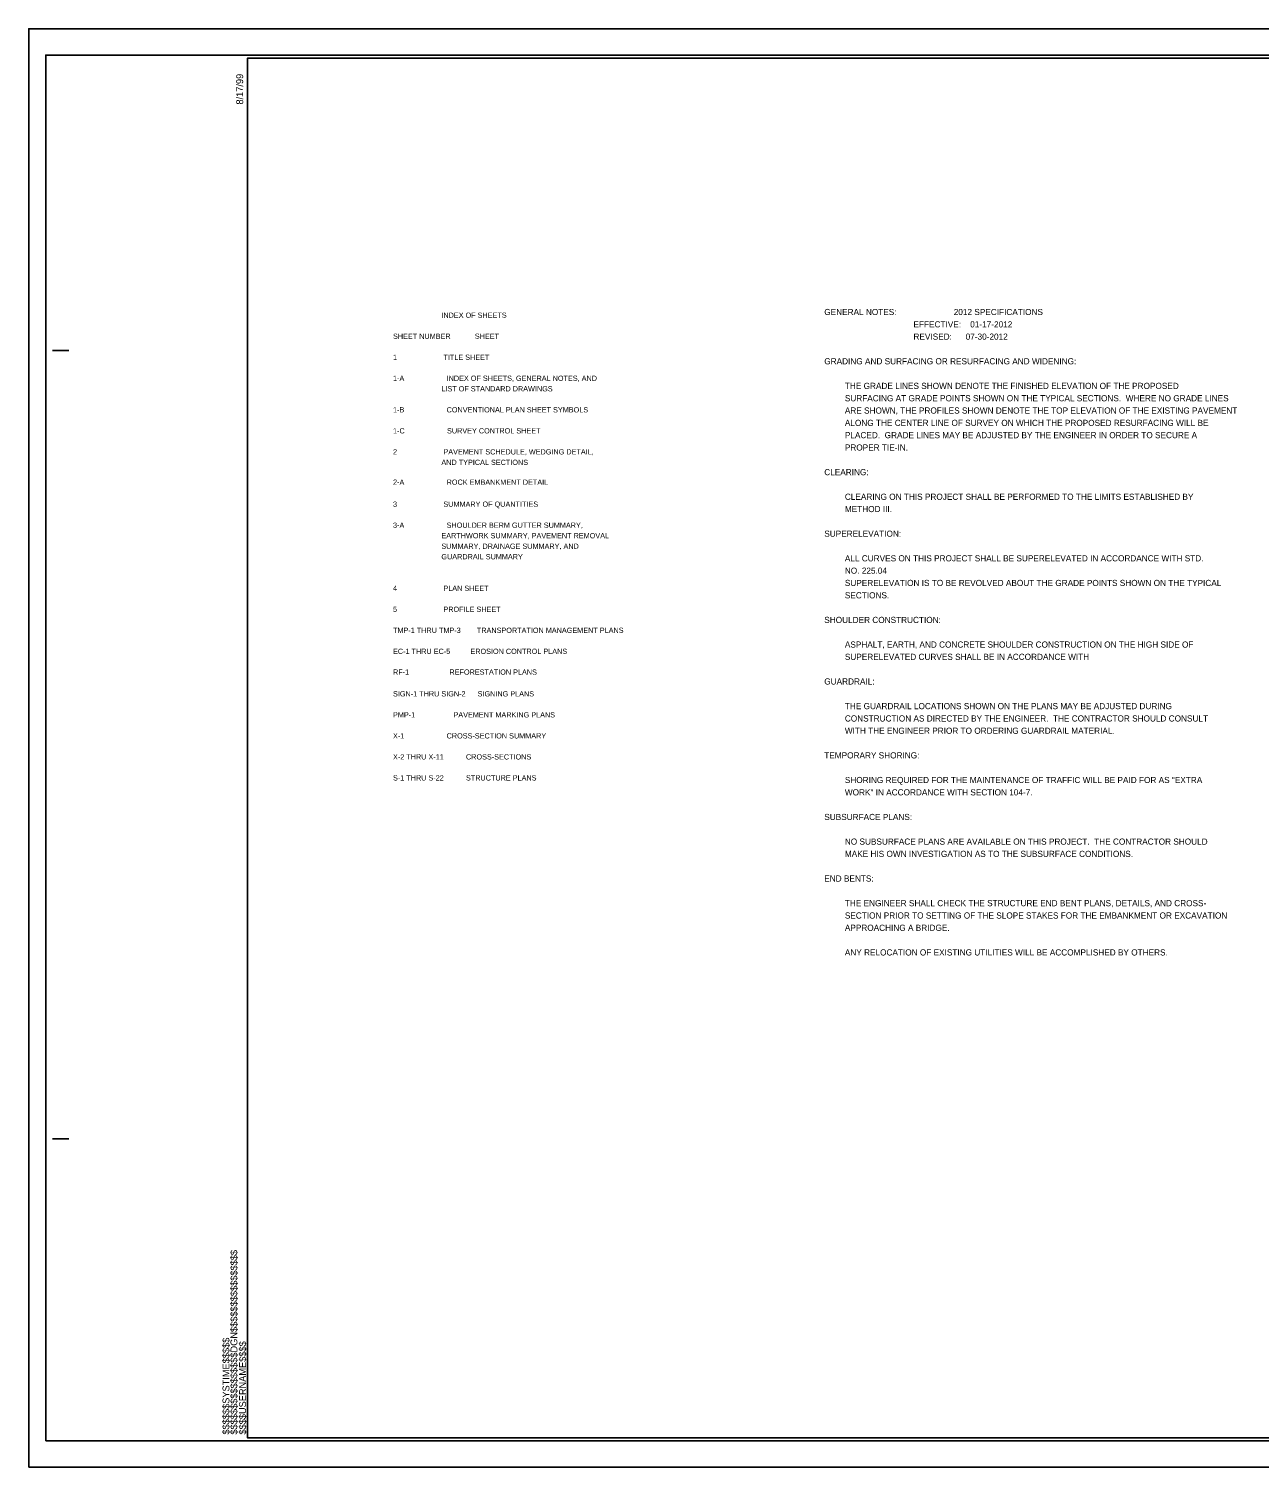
# Model space of a CAD drawing. Extents: x 573852.2 to 573885.9, y -53312.9 to -53240.3.
# Drawn here: x 573852.19 to 573870.93, y -53262.19 to -53240.29 of the extents above; entities that cross this region are included whole.
import ezdxf

# ---------------------------------------------------------------- set-up
doc = ezdxf.new("R2010")
doc.units = 0
for name, color, linetype in [('Default', 7, 'Continuous'), ('Sheet Cutting Line CELL', 7, 'Continuous'), ('Sheet Data Text CELL', 7, 'Continuous'), ('Sheet Plan CELL', 7, 'Continuous'), ('Sheet Plot Border Inside CELL', 7, 'Continuous'), ('Sheet Plot Border Outside CELL', 7, 'Continuous')]:
    doc.layers.add(name, color=color, linetype=linetype)

msp = doc.modelspace()

# ---------------------------------------------------------------- linework, layer by layer
at = {"layer": 'Sheet Cutting Line CELL'}
for p, q in [((573885.861, -53240.29), (573852.191, -53240.29)), ((573852.191, -53240.29), (573852.191, -53262.19)), ((573852.191, -53262.19), (573885.861, -53262.19))]:
    msp.add_line(p, q, dxfattribs=at)
at = {"layer": 'Sheet Plan CELL'}
for p, q in [((573855.521, -53240.74), (573855.521, -53240.74)), ((573852.551, -53245.19), (573852.801, -53245.19)), ((573852.551, -53257.19), (573852.801, -53257.19)), ((573855.521, -53261.74), (573855.521, -53261.74))]:
    msp.add_line(p, q, dxfattribs=at)
msp.add_lwpolyline([(573885.521, -53240.74), (573855.521, -53240.74), (573855.521, -53261.74), (573885.521, -53261.74)], close=True, dxfattribs=at)
at = {"layer": 'Sheet Plot Border Inside CELL'}
msp.add_lwpolyline([(573852.451, -53261.79), (573885.771, -53261.79), (573885.771, -53240.69), (573852.451, -53240.69)], close=True, dxfattribs=at)
at = {"layer": 'Sheet Plot Border Outside CELL'}
msp.add_lwpolyline([(573852.191, -53262.19), (573885.861, -53262.19), (573885.861, -53240.29), (573852.191, -53240.29)], close=True, dxfattribs=at)

# ---------------------------------------------------------------- texts
at = {"layer": 'Default'}
for s, p in [('GENERAL NOTES:                         2012 SPECIFICATIONS', (573864.305, -53244.649)), ('                                       EFFECTIVE:    01-17-2012', (573864.305, -53244.837)), ('                                       REVISED:      07-30-2012', (573864.305, -53245.024)), ('GRADING AND SURFACING OR RESURFACING AND WIDENING:  ', (573864.305, -53245.399)), ('         THE GRADE LINES SHOWN DENOTE THE FINISHED ELEVATION OF THE PROPOSED ', (573864.305, -53245.774)), ('         SURFACING AT GRADE POINTS SHOWN ON THE TYPICAL SECTIONS.  WHERE NO GRADE LINES ', (573864.305, -53245.962)), ('         ARE SHOWN, THE PROFILES SHOWN DENOTE THE TOP ELEVATION OF THE EXISTING PAVEMENT ', (573864.305, -53246.149)), ('         ALONG THE CENTER LINE OF SURVEY ON WHICH THE PROPOSED RESURFACING WILL BE ', (573864.305, -53246.337)), ('         PLACED.  GRADE LINES MAY BE ADJUSTED BY THE ENGINEER IN ORDER TO SECURE A ', (573864.305, -53246.524)), ('         PROPER TIE-IN.  ', (573864.305, -53246.712)), ('CLEARING:  ', (573864.305, -53247.087)), ('         CLEARING ON THIS PROJECT SHALL BE PERFORMED TO THE LIMITS ESTABLISHED BY ', (573864.305, -53247.462)), ('         METHOD III.', (573864.305, -53247.649)), ('SUPERELEVATION:  ', (573864.305, -53248.024)), ('         ALL CURVES ON THIS PROJECT SHALL BE SUPERELEVATED IN ACCORDANCE WITH STD. ', (573864.305, -53248.399)), ('         NO. 225.04', (573864.305, -53248.587)), ('         SUPERELEVATION IS TO BE REVOLVED ABOUT THE GRADE POINTS SHOWN ON THE TYPICAL ', (573864.305, -53248.774)), ('         SECTIONS.  ', (573864.305, -53248.962)), ('SHOULDER CONSTRUCTION:  ', (573864.305, -53249.337)), ('         ASPHALT, EARTH, AND CONCRETE SHOULDER CONSTRUCTION ON THE HIGH SIDE OF', (573864.305, -53249.712)), ('         SUPERELEVATED CURVES SHALL BE IN ACCORDANCE WITH ', (573864.305, -53249.899)), ('GUARDRAIL:  ', (573864.305, -53250.274)), ('         THE GUARDRAIL LOCATIONS SHOWN ON THE PLANS MAY BE ADJUSTED DURING ', (573864.305, -53250.649)), ('         WITH THE ENGINEER PRIOR TO ORDERING GUARDRAIL MATERIAL.', (573864.305, -53251.024)), ('         CONSTRUCTION AS DIRECTED BY THE ENGINEER.  THE CONTRACTOR SHOULD CONSULT', (573864.305, -53250.837)), ('TEMPORARY SHORING:  ', (573864.305, -53251.399)), ('         SHORING REQUIRED FOR THE MAINTENANCE OF TRAFFIC WILL BE PAID FOR AS "EXTRA ', (573864.305, -53251.774)), ('         WORK" IN ACCORDANCE WITH SECTION 104-7.  ', (573864.305, -53251.962)), ('SUBSURFACE PLANS:  ', (573864.305, -53252.337)), ('         NO SUBSURFACE PLANS ARE AVAILABLE ON THIS PROJECT.  THE CONTRACTOR SHOULD ', (573864.305, -53252.712)), ('         MAKE HIS OWN INVESTIGATION AS TO THE SUBSURFACE CONDITIONS.  ', (573864.305, -53252.899)), ('END BENTS:  ', (573864.305, -53253.274)), ('         THE ENGINEER SHALL CHECK THE STRUCTURE END BENT PLANS, DETAILS, AND CROSS-', (573864.305, -53253.649)), ('         SECTION PRIOR TO SETTING OF THE SLOPE STAKES FOR THE EMBANKMENT OR EXCAVATION ', (573864.305, -53253.837)), ('         APPROACHING A BRIDGE.  ', (573864.305, -53254.024)), ('         ANY RELOCATION OF EXISTING UTILITIES WILL BE ACCOMPLISHED BY OTHERS.  ', (573864.305, -53254.399))]:
    msp.add_text(s, height=0.09375, dxfattribs=at).set_placement(p)
at = {"layer": 'Sheet Data Text CELL'}
for s, p in [('                        INDEX OF SHEETS ', (573857.738, -53244.691)), ('SHEET NUMBER            SHEET                                          ', (573857.738, -53245.011)), ('1                       TITLE SHEET', (573857.738, -53245.331)), ('1-A                     INDEX OF SHEETS, GENERAL NOTES, AND', (573857.738, -53245.651)), ('                        LIST OF STANDARD DRAWINGS', (573857.738, -53245.811)), ('1-B                     CONVENTIONAL PLAN SHEET SYMBOLS', (573857.738, -53246.131)), ('1-C                     SURVEY CONTROL SHEET', (573857.738, -53246.451)), ('2                       PAVEMENT SCHEDULE, WEDGING DETAIL,', (573857.738, -53246.771)), ('                        AND TYPICAL SECTIONS', (573857.738, -53246.931)), ('2-A                     ROCK EMBANKMENT DETAIL', (573857.738, -53247.233)), ('3                       SUMMARY OF QUANTITIES', (573857.738, -53247.568)), ('3-A                     SHOULDER BERM GUTTER SUMMARY,', (573857.738, -53247.888)), ('                        EARTHWORK SUMMARY, PAVEMENT REMOVAL', (573857.738, -53248.048)), ('                        SUMMARY, DRAINAGE SUMMARY, AND', (573857.738, -53248.208)), ('                        GUARDRAIL SUMMARY', (573857.738, -53248.368)), ('4                       PLAN SHEET', (573857.738, -53248.848)), ('5                       PROFILE SHEET  ', (573857.738, -53249.168)), ('TMP-1 THRU TMP-3        TRANSPORTATION MANAGEMENT PLANS', (573857.738, -53249.488)), ('EC-1 THRU EC-5          EROSION CONTROL PLANS', (573857.738, -53249.808)), ('RF-1                    REFORESTATION PLANS', (573857.738, -53250.124)), ('SIGN-1 THRU SIGN-2      SIGNING PLANS', (573857.738, -53250.455)), ('PMP-1                   PAVEMENT MARKING PLANS', (573857.738, -53250.775)), ('X-1                     CROSS-SECTION SUMMARY', (573857.738, -53251.095)), ('X-2 THRU X-11           CROSS-SECTIONS', (573857.738, -53251.415)), ('S-1 THRU S-22           STRUCTURE PLANS', (573857.738, -53251.735))]:
    msp.add_text(s, height=0.08, dxfattribs=at).set_placement(p)
at = {"layer": 'Sheet Plan CELL'}
for s, p in [('8/17/99', (573855.456, -53241.444)), ('$$$$$$$$$$$$$$$$DGN$$$$$$$$$$$$$$$$', (573855.368, -53261.693)), ('$$$$$$SYSTIME$$$$$', (573855.247, -53261.693)), ('$$$$USERNAME$$$$', (573855.5, -53261.693))]:
    msp.add_text(s, height=0.105, rotation=90, dxfattribs=at).set_placement(p)

doc.saveas('drawing.dxf')
